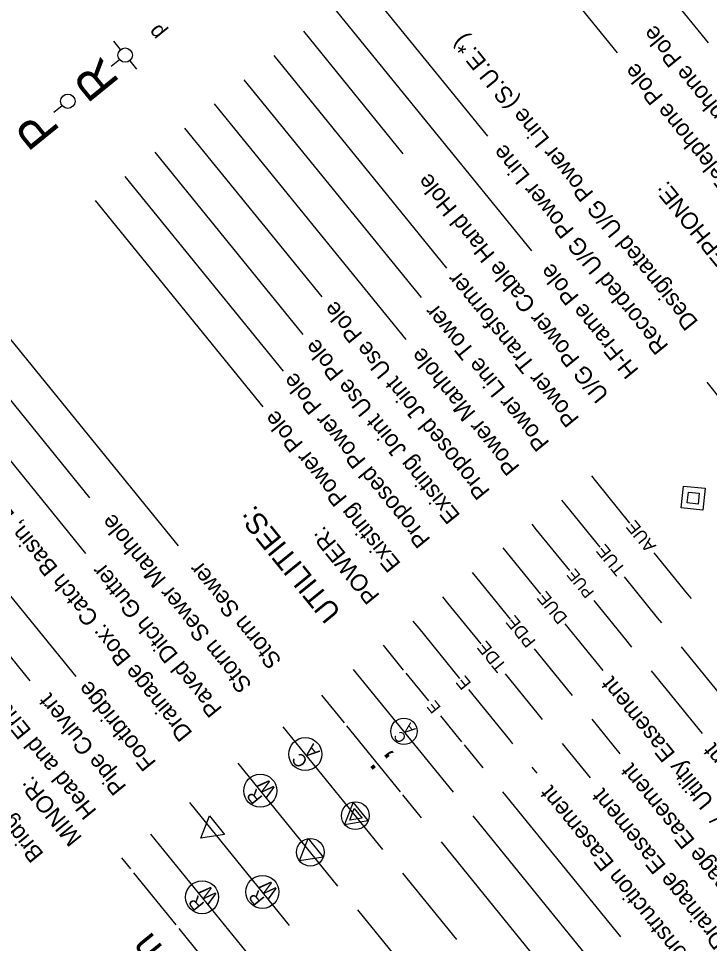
# Model space of a CAD drawing. Extents: x 2596486 to 2602076, y 851390 to 856110.
# Drawn here: x 2599483.7 to 2599844.2, y 854986.6 to 855469.1 of the extents above; entities that cross this region are included whole.
import ezdxf

# ---------------------------------------------------------------- set-up
doc = ezdxf.new("R2010")
doc.units = 0
for name, color, linetype in [('Prop Easement Permanent Drainage Utility', 7, 'Continuous'), ('Prop ROW Permanent Easement CELL', 7, 'Continuous'), ('Sheet Symbology CELL', 7, 'Continuous')]:
    doc.layers.add(name, color=color, linetype=linetype)

msp = doc.modelspace()

# ---------------------------------------------------------------- linework, layer by layer
at = {"layer": 'Prop Easement Permanent Drainage Utility'}
for p, q in [((2599756.26, 855168.8), (2599736.58, 855193.01)), ((2599788.62, 855128.99), (2599768.87, 855153.28))]:
    msp.add_line(p, q, dxfattribs=at)
at = {"layer": 'Prop ROW Permanent Easement CELL'}
msp.add_line((2599835.66, 855218.96), (2599835.66, 855218.96), dxfattribs=at)
for points in [[(2599829.41, 855213.88), (2599830.58, 855225.21), (2599841.91, 855224.04), (2599840.74, 855212.71)], [(2599832.54, 855216.42), (2599833.12, 855222.08), (2599838.78, 855221.5), (2599838.2, 855215.83)]]:
    msp.add_lwpolyline(points, close=True, dxfattribs=at)
at = {"layer": 'Sheet Symbology CELL'}
for p, q in [((2599756.52, 855563.33), (2599843.47, 855456.35)), ((2599725.48, 855538.1), (2599796.04, 855451.28)), ((2599663.39, 855487.65), (2599728.33, 855407.75)), ((2599647.87, 855475.03), (2599751.25, 855347.84)), ((2599632.35, 855462.42), (2599684.28, 855398.53)), ((2599536.99, 855452.9), (2599533.44, 855457.26)), ((2599616.83, 855449.8), (2599706.96, 855338.91)), ((2599536.44, 855447.62), (2599532.08, 855444.08)), ((2599541.72, 855447.08), (2599545.26, 855442.71)), ((2599601.31, 855437.19), (2599693.71, 855323.5)), ((2599506.55, 855423.6), (2599502.18, 855420.05)), ((2599585.79, 855424.58), (2599685.76, 855301.58)), ((2599570.27, 855411.96), (2599641.87, 855323.87)), ((2599554.75, 855399.35), (2599632.02, 855304.28)), ((2599539.23, 855386.73), (2599621.8, 855285.14)), ((2599523.71, 855374.12), (2599611.19, 855266.49)), ((2599463.39, 855321.5), (2599566.95, 855194.08)), ((2599447.87, 855308.88), (2599520.83, 855219.12)), ((2599432.35, 855296.27), (2599518.72, 855189.99)), ((2599850.45, 855270.1), (2599842.88, 855279.41)), ((2599397.87, 855268.25), (2599513.59, 855125.87)), ((2599382.35, 855255.63), (2599489.69, 855123.56)), ((2599785.32, 855227.27), (2599782.7, 855230.49)), ((2599802.66, 855205.93), (2599785.32, 855227.27)), ((2599769.8, 855214.66), (2599767.18, 855217.88)), ((2599787.14, 855193.32), (2599769.8, 855214.66)), ((2599753.97, 855202.42), (2599751.66, 855205.27)), ((2599771.31, 855181.08), (2599753.97, 855202.42)), ((2599832.62, 855169.07), (2599815.27, 855190.41)), ((2599722.94, 855177.16), (2599720.61, 855180.03)), ((2599740.29, 855155.82), (2599722.94, 855177.16)), ((2599817.1, 855156.46), (2599799.75, 855177.8)), ((2599707.71, 855164.2), (2599705.09, 855167.42)), ((2599801.27, 855144.22), (2599783.93, 855165.56)), ((2599834.73, 855166.47), (2599832.62, 855169.07)), ((2599725.05, 855142.86), (2599707.71, 855164.2)), ((2599819.21, 855153.86), (2599817.1, 855156.46)), ((2599692.65, 855151.01), (2599689.57, 855154.8)), ((2599713.94, 855124.82), (2599692.65, 855151.01)), ((2599684.61, 855129.2), (2599674.05, 855142.19)), ((2599803.69, 855141.24), (2599801.27, 855144.22)), ((2599829.32, 855141.42), (2599855.9, 855108.72)), ((2599770.25, 855118.96), (2599752.9, 855140.3)), ((2599710.56, 855065.55), (2599658.53, 855129.57)), ((2599697.69, 855113.1), (2599685.87, 855127.65)), ((2599755.01, 855106), (2599737.67, 855127.34)), ((2599813.8, 855128.8), (2599840.38, 855096.11)), ((2599739.96, 855092.81), (2599718.67, 855119)), ((2599772.64, 855116.01), (2599770.25, 855118.96)), ((2599653.71, 855101.66), (2599641.96, 855116.11)), ((2599715.04, 855091.76), (2599704, 855105.34)), ((2599757.12, 855103.4), (2599755.01, 855106)), ((2599782.75, 855103.57), (2599797.36, 855085.61)), ((2599673.76, 855035.64), (2599621.72, 855099.66)), ((2599682.98, 855065.64), (2599654.97, 855100.1)), ((2599741.6, 855090.78), (2599739.96, 855092.81)), ((2599726.08, 855078.17), (2599716.3, 855090.21)), ((2599767.23, 855090.96), (2599781.84, 855072.99)), ((2599650.28, 855016.56), (2599598.25, 855080.58)), ((2599751.47, 855078.64), (2599754.11, 855075.4)), ((2599693.99, 855052.09), (2599684.24, 855064.09)), ((2599736.19, 855065.73), (2599797.72, 854990.03)), ((2599625.06, 854996.06), (2599573.03, 855060.08)), ((2599659.44, 855053.25), (2599659.44, 855053.25)), ((2599720.67, 855053.11), (2599782.2, 854977.41)), ((2599584.41, 855046.08), (2599584.41, 855046.08)), ((2599604.79, 854979.59), (2599552.76, 855043.61)), ((2599704.11, 855039.65), (2599765.63, 854963.95)), ((2599542.32, 855025.46), (2599537.59, 855031.28)), ((2599635.97, 855034.18), (2599635.97, 855034.18)), ((2599565.97, 854996.36), (2599543.89, 855023.52)), ((2599683.97, 855023.28), (2599712.11, 854988.66)), ((2599660.5, 855004.21), (2599688.88, 854969.3)), ((2599589.62, 854967.26), (2599567.54, 854994.42))]:
    msp.add_line(p, q, dxfattribs=at)
for points in [[(2599666.17, 855050.67), (2599658.29, 855060.37), (2599653.85, 855048.71)], [(2599662.96, 855051.9), (2599656.52, 855050.88), (2599658.84, 855056.98)], [(2599591.15, 855043.5), (2599578.83, 855041.54), (2599583.27, 855053.2)], [(2599642.7, 855031.6), (2599630.38, 855029.64), (2599634.82, 855041.3)]]:
    msp.add_lwpolyline(points, close=True, dxfattribs=at)
for centre, radius in [((2599539.36, 855450), 3.75), ((2599509.46, 855425.97), 3.75), ((2599684.78, 855097.27), 6.89), ((2599633.33, 855085.38), 8.61), ((2599609.86, 855066.3), 8.61), ((2599659.44, 855053.25), 7.2), ((2599635.97, 855034.18), 7.2), ((2599610.92, 855013.46), 8.61), ((2599579.49, 855010.72), 8.61)]:
    msp.add_circle(centre, radius, dxfattribs=at)

# ---------------------------------------------------------------- texts
at = {"layer": 'Prop Easement Permanent Drainage Utility'}
msp.add_text('DUE', height=6.55, rotation=129.1028, dxfattribs=at).set_placement((2599770.43, 855156.6))
at = {"layer": 'Sheet Symbology CELL'}
for s, height, p in [('p', 8.25, (2599560.68, 855462.01)), ('Proposed Telephone Pole', 8.75, (2599900.75, 855361.35)), ('Designated U/G Power Line (S.U.E.*)', 8.75, (2599838.65, 855310.9)), ('R', 18.75, (2599537.03, 855436.02)), ('Existing Telephone Pole', 8.75, (2599885.23, 855348.74)), ('P', 18.75, (2599505.99, 855410.79)), ('Recorded U/G Power Line', 8.75, (2599823.15, 855298.28)), ('U/G Power Cable Hand Hole', 8.75, (2599792.11, 855273.05)), ('TELEPHONE:', 8.75, (2599868.74, 855327.52)), ('H-Frame Pole', 8.75, (2599807.63, 855285.67)), ('Power Transformer', 8.75, (2599776.6, 855260.41)), ('Proposed Joint Use Pole', 8.75, (2599730.04, 855222.59)), ('Power Line Tower', 8.75, (2599761.07, 855247.81)), ('Existing Joint Use Pole', 8.75, (2599714.52, 855209.95)), ('Power Manhole', 8.75, (2599745.56, 855235.2)), ('Proposed Power Pole', 8.75, (2599699, 855197.35)), ('Existing Power Pole', 8.75, (2599683.48, 855184.73)), ('Drainage Box: Catch Basin, DI or JB', 8.75, (2599574.84, 855096.43)), ('UTILITIES:', 11, (2599652.46, 855159.5)), ('Storm Sewer Manhole', 8.75, (2599605.89, 855121.67)), ('Bridge Wing Wall, Head Wall and End Wall', 8.75, (2599497.26, 855033.36)), ('POWER:', 8.75, (2599672.55, 855168.06)), ('AUE', 6.55, (2599816.62, 855193.99)), ('TUE', 6.55, (2599800.69, 855181.88)), ('Storm Sewer', 8.75, (2599621.41, 855134.28)), ('Paved Ditch Gutter', 8.75, (2599590.37, 855109.05)), ('PUE', 6, (2599784.3, 855169.86)), ('CONVENTIONAL  PLAN SHEET SYMBOLS', 27.2003, (2599572.48, 854624.06)), ('PDE', 6.55, (2599753.89, 855144.32)), ('TDE', 6.55, (2599738.59, 855131.43)), ('Head and End Wall', 8.75, (2599524.86, 855055.79)), ('E', 6.55, (2599720.22, 855122.32)), ('Proposed Permanent Drainage /  Utility Easement', 8.75, (2599956.74, 854925.72)), ('Footbridge', 8.75, (2599555.88, 855081.02)), ('Pipe Culvert', 8.75, (2599540.37, 855068.4)), ('E', 6, (2599704.31, 855109.71)), ('A', 5.4, (2599691.16, 855098.43)), ('C', 5.4, (2599686.46, 855093.92)), ('A', 6.75, (2599641.25, 855086.63)), ('Proposed Permanent Utility Easement', 8.75, (2599971.82, 854937.97)), ('C', 6.75, (2599635.04, 855081.66)), (';', 15, (2599678.53, 855083.01)), ('Proposed Permanent Drainage Easement', 8.75, (2599940.77, 854912.74)), ('MINOR:', 8.75, (2599517.21, 855041.81)), ('W', 6.75, (2599618.55, 855066.61)), ('Proposed Temporary Construction Easement', 8.75, (2599909.73, 854887.51)), ('R', 6.75, (2599611.41, 855062.78)), ('Proposed Temporary Drainage Easement', 8.75, (2599925.25, 854900.13)), ('W', 6.75, (2599588.18, 855011.02)), ('W', 6.75, (2599619.62, 855013.77)), ('R', 6.75, (2599581.04, 855007.2)), ('R', 6.75, (2599612.48, 855009.95)), ('h', 15, (2599559.41, 854984.6))]:
    msp.add_text(s, height=height, rotation=129.1028, dxfattribs=at).set_placement(p)

doc.saveas('drawing.dxf')
